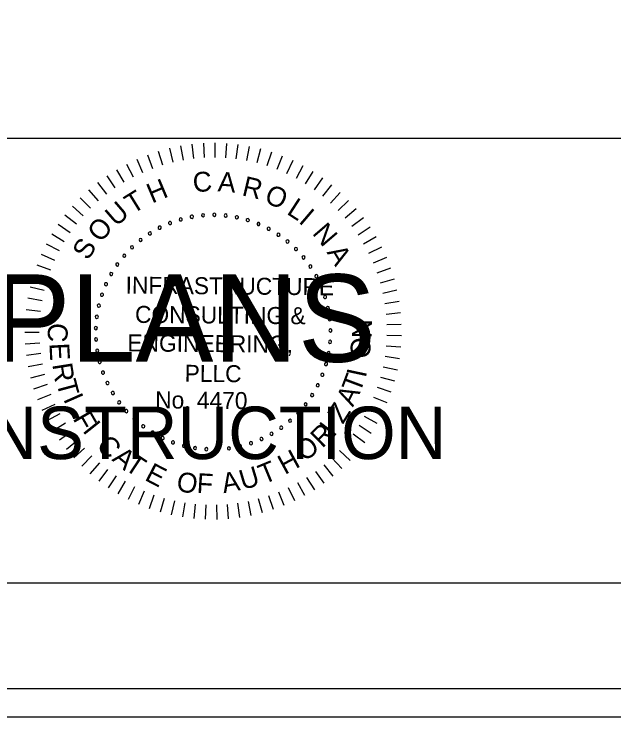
# Model space of a CAD drawing. Extents: x 967 to 1623, y 964 to 7064.
# Drawn here: x 1189.3 to 1212.88, y 963.72 to 991.36 of the extents above; entities that cross this region are included whole.
import ezdxf

# ---------------------------------------------------------------- set-up
doc = ezdxf.new("R2010")
doc.units = 0
for name, color, linetype in [('RD_SHT_Bndy', 7, 'Continuous'), ('RD_SHT_IplotShp', 7, 'Continuous'), ('RD_SHT_Misc1', 7, 'Continuous'), ('RD_SHT_Misc2', 7, 'Continuous'), ('RD_Sketch1', 7, 'Continuous')]:
    doc.layers.add(name, color=color, linetype=linetype)

msp = doc.modelspace()

# ---------------------------------------------------------------- linework, layer by layer
at = {"layer": 'RD_SHT_Bndy'}
for p, q in [((996.114, 986.486), (1323.886, 986.486)), ((1323.886, 968.983), (996.114, 968.983))]:
    msp.add_line(p, q, dxfattribs=at)
at = {"layer": 'RD_SHT_IplotShp'}
for points in [[(967.409, 963.72), (1326.285, 963.72), (1326.285, 1183.72), (967.409, 1183.72)], [(988.525, 964.84), (1326.285, 964.84), (1326.285, 1182.6), (988.525, 1182.6)]]:
    msp.add_lwpolyline(points, close=True, dxfattribs=at)
at = {"layer": 'RD_SHT_Misc1'}
for p, q in [((1196.292, 986.245), (1196.357, 985.68)), ((1196.742, 986.282), (1196.772, 985.714)), ((1197.194, 986.292), (1197.189, 985.723)), ((1197.645, 986.274), (1197.606, 985.706)), ((1198.094, 986.228), (1198.02, 985.664)), ((1194.968, 985.971), (1195.134, 985.427)), ((1195.403, 986.09), (1195.536, 985.536)), ((1195.846, 986.181), (1195.945, 985.62)), ((1198.54, 986.156), (1198.432, 985.596)), ((1198.98, 986.056), (1198.838, 985.504)), ((1199.414, 985.929), (1199.238, 985.387)), ((1194.122, 985.656), (1194.353, 985.136)), ((1194.54, 985.827), (1194.739, 985.293)), ((1199.839, 985.777), (1199.63, 985.246)), ((1193.715, 985.461), (1193.978, 984.956)), ((1200.253, 985.598), (1200.013, 985.082)), ((1200.656, 985.395), (1200.385, 984.894)), ((1193.321, 985.241), (1193.614, 984.752)), ((1201.047, 985.167), (1200.745, 984.684)), ((1192.94, 984.997), (1193.263, 984.528)), ((1201.422, 984.917), (1201.092, 984.453)), ((1192.576, 984.731), (1192.926, 984.282)), ((1201.781, 984.643), (1201.424, 984.2)), ((1192.228, 984.443), (1192.605, 984.016)), ((1202.124, 984.349), (1201.739, 983.928)), ((1191.899, 984.134), (1192.301, 983.731)), ((1202.447, 984.034), (1202.038, 983.638)), ((1191.589, 983.805), (1192.015, 983.428)), ((1202.751, 983.7), (1202.318, 983.329)), ((1191.299, 983.459), (1191.748, 983.108)), ((1203.034, 983.348), (1202.579, 983.004)), ((1191.032, 983.095), (1191.501, 982.772)), ((1203.294, 982.979), (1202.82, 982.664)), ((1190.787, 982.716), (1191.274, 982.422)), ((1203.532, 982.595), (1203.04, 982.31)), ((1190.565, 982.323), (1191.07, 982.059)), ((1203.746, 982.198), (1203.237, 981.943)), ((1190.368, 981.916), (1190.888, 981.684)), ((1203.936, 981.788), (1203.412, 981.564)), ((1190.196, 981.499), (1190.729, 981.299)), ((1204.1, 981.367), (1203.563, 981.176)), ((1190.05, 981.072), (1190.594, 980.905)), ((1204.238, 980.937), (1203.691, 980.779)), ((1189.93, 980.636), (1190.484, 980.503)), ((1204.349, 980.5), (1203.794, 980.375)), ((1189.837, 980.195), (1190.398, 980.095)), ((1204.434, 980.056), (1203.872, 979.966)), ((1189.771, 979.748), (1190.337, 979.683)), ((1204.491, 979.608), (1203.925, 979.552)), ((1189.732, 979.298), (1190.301, 979.267)), ((1204.522, 979.158), (1203.953, 979.137)), ((1189.721, 978.847), (1190.29, 978.851)), ((1204.524, 978.706), (1203.955, 978.72)), ((1189.737, 978.396), (1190.306, 978.434)), ((1204.499, 978.256), (1203.932, 978.304)), ((1189.781, 977.946), (1190.346, 978.019)), ((1204.447, 977.807), (1203.884, 977.89)), ((1189.852, 977.5), (1190.412, 977.608)), ((1204.367, 977.363), (1203.81, 977.479)), ((1189.951, 977.06), (1190.502, 977.201)), ((1204.261, 976.924), (1203.712, 977.074)), ((1190.076, 976.626), (1190.617, 976.8)), ((1204.128, 976.492), (1203.589, 976.676)), ((1190.227, 976.2), (1190.757, 976.408)), ((1203.969, 976.07), (1203.442, 976.286)), ((1190.403, 975.785), (1190.92, 976.024)), ((1203.784, 975.658), (1203.271, 975.906)), ((1190.605, 975.381), (1191.106, 975.651)), ((1203.574, 975.258), (1203.078, 975.537)), ((1190.831, 974.99), (1191.315, 975.291)), ((1203.341, 974.871), (1202.862, 975.18)), ((1191.081, 974.614), (1191.545, 974.943)), ((1191.353, 974.253), (1191.796, 974.61)), ((1203.085, 974.5), (1202.626, 974.837)), ((1202.806, 974.145), (1202.368, 974.509)), ((1191.646, 973.91), (1192.067, 974.293)), ((1202.506, 973.807), (1202.092, 974.197)), ((1191.96, 973.585), (1192.356, 973.994)), ((1202.186, 973.488), (1201.796, 973.903)), ((1192.293, 973.28), (1192.664, 973.712)), ((1201.847, 973.19), (1201.484, 973.628)), ((1192.644, 972.996), (1192.988, 973.45)), ((1193.011, 972.734), (1193.327, 973.208)), ((1201.491, 972.912), (1201.155, 973.372)), ((1193.394, 972.495), (1193.68, 972.987)), ((1200.731, 972.425), (1200.453, 972.922)), ((1201.119, 972.657), (1200.811, 973.136)), ((1193.791, 972.279), (1194.047, 972.788)), ((1200.331, 972.217), (1200.083, 972.73)), ((1194.2, 972.088), (1194.424, 972.612)), ((1194.62, 971.923), (1194.812, 972.459)), ((1199.495, 971.877), (1199.312, 972.416)), ((1199.918, 972.034), (1199.702, 972.561)), ((1195.05, 971.783), (1195.208, 972.33)), ((1195.487, 971.67), (1195.612, 972.225)), ((1195.93, 971.584), (1196.021, 972.146)), ((1196.377, 971.524), (1196.434, 972.091)), ((1198.179, 971.562), (1198.097, 972.126)), ((1198.624, 971.64), (1198.508, 972.198)), ((1199.063, 971.745), (1198.913, 972.295)), ((1196.828, 971.493), (1196.85, 972.062)), ((1197.279, 971.488), (1197.267, 972.058)), ((1197.73, 971.512), (1197.683, 972.079))]:
    msp.add_line(p, q, dxfattribs=at)
for centre, start, end in [((1196.285, 983.388), 10.6038, 190.6038), ((1196.727, 983.447), 5.0653, 185.0653), ((1196.727, 983.447), 185.0653, 5.0653), ((1197.172, 983.464), 359.5268, 179.5268), ((1197.172, 983.464), 179.5268, 359.5268), ((1197.617, 983.438), 173.9884, 353.9884), ((1197.617, 983.438), 353.9884, 173.9884), ((1198.057, 983.369), 348.4499, 168.4499), ((1195.429, 983.142), 21.6807, 201.6807), ((1195.429, 983.142), 201.6807, 21.6807), ((1195.851, 983.285), 16.1422, 196.1422), ((1195.851, 983.285), 196.1422, 16.1422), ((1196.285, 983.388), 190.6038, 10.6038), ((1198.057, 983.369), 168.4499, 348.4499), ((1198.489, 983.258), 162.9114, 342.9114), ((1198.489, 983.258), 342.9114, 162.9114), ((1198.908, 983.106), 337.373, 157.373), ((1195.023, 982.958), 27.2191, 207.2191), ((1195.023, 982.958), 207.2191, 27.2191), ((1198.908, 983.106), 157.373, 337.373), ((1199.31, 982.914), 151.8345, 331.8345), ((1199.31, 982.914), 331.8345, 151.8345), ((1194.637, 982.736), 32.7576, 212.7576), ((1194.637, 982.736), 212.7576, 32.7576), ((1199.692, 982.684), 146.2961, 326.2961), ((1199.692, 982.684), 326.2961, 146.2961), ((1194.274, 982.478), 38.2961, 218.2961), ((1194.274, 982.478), 218.2961, 38.2961), ((1200.05, 982.419), 140.7576, 320.7576), ((1200.05, 982.419), 320.7576, 140.7576), ((1193.937, 982.186), 43.8345, 223.8345), ((1193.937, 982.186), 223.8345, 43.8345), ((1200.38, 982.12), 135.2191, 315.2191), ((1200.38, 982.12), 315.2191, 135.2191), ((1193.63, 981.862), 49.373, 229.373), ((1193.63, 981.862), 229.373, 49.373), ((1200.68, 981.79), 129.6807, 309.6807), ((1200.68, 981.79), 309.6807, 129.6807), ((1193.356, 981.511), 54.9114, 234.9114), ((1193.356, 981.511), 234.9114, 54.9114), ((1200.947, 981.433), 304.1422, 124.1422), ((1200.947, 981.433), 124.1422, 304.1422), ((1193.117, 981.135), 60.4499, 240.4499), ((1193.117, 981.135), 240.4499, 60.4499), ((1201.179, 981.052), 118.6038, 298.6038), ((1201.179, 981.052), 298.6038, 118.6038), ((1192.915, 980.737), 65.9884, 245.9884), ((1192.915, 980.737), 245.9884, 65.9884), ((1201.372, 980.651), 113.0653, 293.0653), ((1201.372, 980.651), 293.0653, 113.0653), ((1192.753, 980.322), 71.5268, 251.5268), ((1192.753, 980.322), 251.5268, 71.5268), ((1201.526, 980.233), 107.5268, 287.5268), ((1201.526, 980.233), 287.5268, 107.5268), ((1192.632, 979.894), 77.0653, 257.0653), ((1192.632, 979.894), 257.0653, 77.0653), ((1201.638, 979.801), 101.9884, 281.9884), ((1201.638, 979.801), 281.9884, 101.9884), ((1192.552, 979.455), 82.6038, 262.6038), ((1192.552, 979.455), 262.6038, 82.6038), ((1201.709, 979.361), 96.4499, 276.4499), ((1201.709, 979.361), 276.4499, 96.4499), ((1192.515, 979.011), 88.1422, 268.1422), ((1192.515, 979.011), 268.1422, 88.1422), ((1201.737, 978.917), 90.9114, 270.9114), ((1201.737, 978.917), 270.9114, 90.9114), ((1192.522, 978.565), 93.6807, 273.6807), ((1192.522, 978.565), 273.6807, 93.6807), ((1201.721, 978.471), 85.373, 265.373), ((1201.721, 978.471), 265.373, 85.373), ((1192.571, 978.122), 99.2191, 279.2191), ((1192.571, 978.122), 279.2191, 99.2191), ((1201.663, 978.029), 79.8345, 259.8345), ((1201.663, 978.029), 259.8345, 79.8345), ((1192.662, 977.686), 104.7576, 284.7576), ((1192.662, 977.686), 284.7576, 104.7576), ((1201.563, 977.595), 74.2961, 254.2961), ((1201.563, 977.595), 254.2961, 74.2961), ((1192.796, 977.261), 110.2961, 290.2961), ((1192.796, 977.261), 290.2961, 110.2961), ((1201.42, 977.173), 68.7576, 248.7576), ((1201.42, 977.173), 248.7576, 68.7576), ((1192.97, 976.851), 115.8345, 295.8345), ((1192.97, 976.851), 295.8345, 115.8345), ((1201.238, 976.766), 63.2191, 243.2191), ((1201.238, 976.766), 243.2191, 63.2191), ((1193.182, 976.459), 301.373, 121.373), ((1193.182, 976.459), 121.373, 301.373), ((1201.018, 976.379), 57.6807, 237.6807), ((1201.018, 976.379), 237.6807, 57.6807), ((1193.432, 976.09), 126.9114, 306.9114), ((1193.432, 976.09), 306.9114, 126.9114), ((1200.761, 976.014), 52.1422, 232.1422), ((1200.761, 976.014), 232.1422, 52.1422), ((1193.715, 975.746), 132.4499, 312.4499), ((1193.715, 975.746), 312.4499, 132.4499), ((1200.47, 975.677), 46.6038, 226.6038), ((1200.47, 975.677), 226.6038, 46.6038), ((1194.031, 975.431), 137.9884, 317.9884), ((1194.031, 975.431), 317.9884, 137.9884), ((1200.148, 975.369), 41.0653, 221.0653), ((1200.148, 975.369), 221.0653, 41.0653), ((1194.376, 975.149), 143.5268, 323.5268), ((1194.376, 975.149), 323.5268, 143.5268), ((1199.798, 975.093), 35.5268, 215.5268), ((1194.746, 974.901), 149.0653, 329.0653), ((1194.746, 974.901), 329.0653, 149.0653), ((1199.422, 974.853), 29.9884, 209.9884), ((1199.422, 974.853), 209.9884, 29.9884), ((1199.798, 975.093), 215.5268, 35.5268), ((1195.139, 974.69), 154.6038, 334.6038), ((1195.139, 974.69), 334.6038, 154.6038), ((1195.55, 974.517), 340.1422, 160.1422), ((1199.026, 974.65), 24.4499, 204.4499), ((1199.026, 974.65), 204.4499, 24.4499), ((1195.55, 974.517), 160.1422, 340.1422), ((1195.975, 974.386), 165.6807, 345.6807), ((1195.975, 974.386), 345.6807, 165.6807), ((1196.412, 974.295), 171.2191, 351.2191), ((1196.412, 974.295), 351.2191, 171.2191), ((1196.855, 974.248), 356.7576, 176.7576), ((1197.301, 974.243), 2.2961, 182.2961), ((1197.745, 974.282), 7.8345, 187.8345), ((1198.183, 974.363), 13.373, 193.373), ((1198.183, 974.363), 193.373, 13.373), ((1198.611, 974.486), 18.9114, 198.9114), ((1198.611, 974.486), 198.9114, 18.9114), ((1196.855, 974.248), 176.7576, 356.7576), ((1197.301, 974.243), 182.2961, 2.2961), ((1197.745, 974.282), 187.8345, 7.8345)]:
    msp.add_arc(centre, 0.0627, start, end, dxfattribs=at)
at = {"layer": 'RD_Sketch1'}
msp.add_lwpolyline([(967.409, 963.72), (1326.285, 963.72), (1326.285, 1183.72), (967.409, 1183.72)], close=True, dxfattribs=at)

# ---------------------------------------------------------------- texts
at = {"layer": 'RD_SHT_Misc1'}
for s, height, rotation, p in [('C', 0.78, 4.7281, (1196.355, 984.346)), ('A', 0.78, 355.6981, (1197.29, 984.39)), ('H', 0.78, 22.7882, (1194.72, 983.904)), ('R', 0.78, 346.6681, (1198.222, 984.238)), ('O', 0.78, 337.638, (1199.096, 983.972)), ('T', 0.78, 31.8182, (1193.961, 983.478)), ('U', 0.78, 40.8482, (1193.306, 982.976)), ('L', 0.78, 327.108, (1199.981, 983.52)), ('I', 0.78, 319.578, (1200.451, 983.182)), ('O', 0.78, 49.8782, (1192.707, 982.341)), ('N', 0.78, 310.548, (1200.994, 982.728)), ('S', 0.78, 58.9083, (1192.211, 981.642)), ('A', 0.78, 301.5179, (1201.576, 981.991)), ('INFRASTRUCTURE', 0.66873, 359.5268, (1193.682, 980.367)), ('CONSULTING &', 0.66873, 359.5268, (1194.051, 979.217)), ('N', 0.78, 89.2085, (1203.359, 978.604)), ('C', 0.78, 267.025, (1190.646, 979.227)), ('ENGINEERING,', 0.66873, 359.5268, (1193.751, 978.095)), ('O', 0.78, 83.2085, (1203.26, 977.786)), ('E', 0.78, 273.025, (1190.685, 978.408)), ('R', 0.78, 279.025, (1190.799, 977.583)), ('PLLC', 0.6687, 359.5268, (1196.002, 976.9)), ('I', 0.78, 77.9093, (1203.121, 977.032)), ('T', 0.78, 69.3954, (1202.891, 976.428)), ('T', 0.78, 285.025, (1190.955, 976.878)), ('No. 4470', 0.6687, 359.5268, (1194.843, 975.855)), ('A', 0.78, 63.3954, (1202.616, 975.888)), ('I', 0.78, 293.7713, (1191.221, 976.225)), ('Z', 0.78, 57.3954, (1202.224, 975.206)), ('F', 0.78, 299.7713, (1191.589, 975.455)), ('I', 0.78, 308.5268, (1191.965, 974.973)), ('R', 0.78, 44.5268, (1201.415, 974.267)), ('I', 0.78, 52.3339, (1201.856, 974.69)), ('C', 0.78, 314.5268, (1192.496, 974.346)), ('O', 0.78, 38.5268, (1200.73, 973.731)), ('A', 0.78, 320.5268, (1193.115, 973.822)), ('T', 0.78, 326.5268, (1193.602, 973.478)), ('H', 0.78, 28.5268, (1199.942, 973.23)), ('T', 0.78, 22.5268, (1199.108, 972.856)), ('E', 0.78, 332.5268, (1194.394, 973.051)), ('U', 0.78, 16.5268, (1198.288, 972.638)), ('O', 0.78, 350.5268, (1195.647, 972.614)), ('F', 0.78, 356.5268, (1196.465, 972.532)), ('A', 0.78, 10.5268, (1197.537, 972.517))]:
    msp.add_text(s, height=height, rotation=rotation, dxfattribs=at).set_placement(p)
at = {"layer": 'RD_SHT_Misc2'}
for s, height, p in [('FINAL PLANS', 3.4375, (1174.145, 977.685)), ('NOT FOR CONSTRUCTION', 2.0625, (1170.901, 973.86))]:
    msp.add_text(s, height=height, dxfattribs=at).set_placement(p)

doc.saveas('drawing.dxf')
